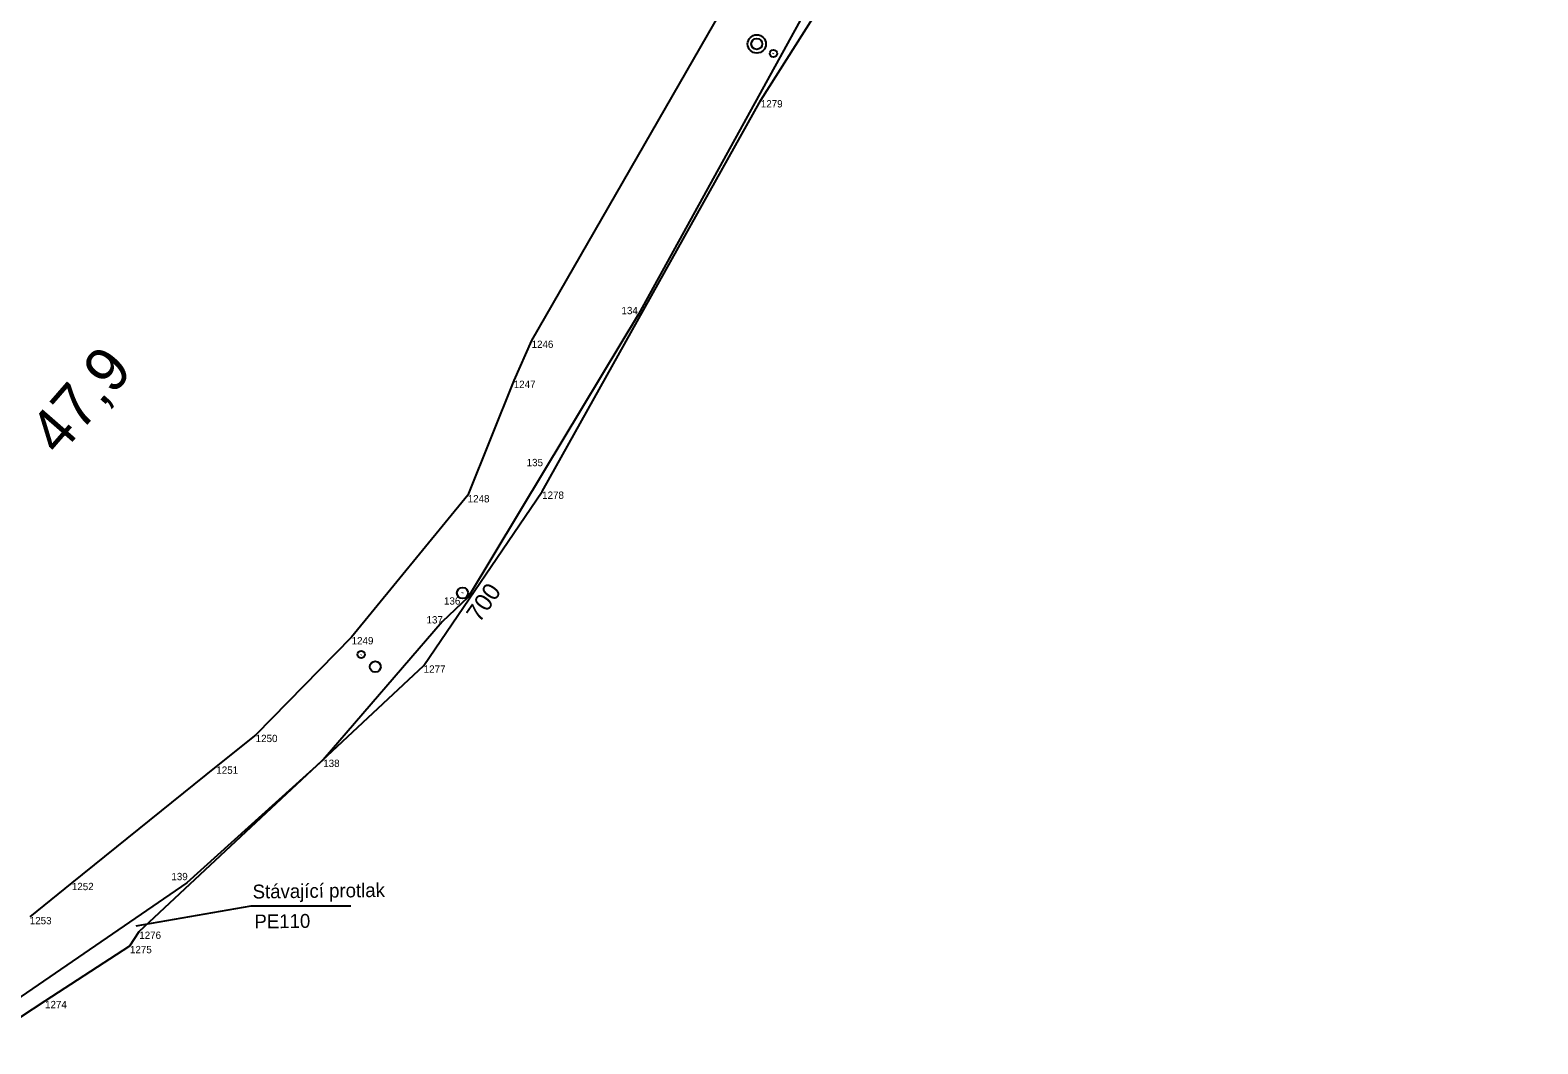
# Model space of a CAD drawing. Extents: x -679938 to -678300, y -1007495 to -1006487.
# Drawn here: x -679528.4 to -679322.3, y -1007219.5 to -1007081 of the extents above; entities that cross this region are included whole.
import ezdxf

# ---------------------------------------------------------------- set-up
doc = ezdxf.new("R2010")
doc.units = 0
for name, color, linetype in [('SSZT nové - lomové body', 7, 'Continuous'), ('SSZT_nové', 7, 'Continuous'), ('Stávající ŽBP', 7, 'Continuous'), ('SŽDC', 7, 'Continuous'), ('SŽDC - body', 7, 'Continuous'), ('Vrstva 7', 7, 'Continuous')]:
    doc.layers.add(name, color=color, linetype=linetype)

msp = doc.modelspace()

# ---------------------------------------------------------------- linework, layer by layer
at = {"layer": 'SSZT nové - lomové body'}
for p, q in [((-679445.24, -1007119.78), (-679445.24, -1007119.78)), ((-679458.14, -1007141.2), (-679458.14, -1007141.2)), ((-679468.52, -1007158.46), (-679468.52, -1007158.46)), ((-679472.05, -1007161.83), (-679472.05, -1007161.83)), ((-679488.31, -1007180.65), (-679488.31, -1007180.65)), ((-679506.94, -1007197.49), (-679506.94, -1007197.49))]:
    msp.add_line(p, q, dxfattribs=at)
at = {"layer": 'SSZT_nové'}
for p, q in [((-679498.2, -1007200.68), (-679513.9, -1007203.39)), ((-679484.54, -1007200.68), (-679498.2, -1007200.68))]:
    msp.add_line(p, q, dxfattribs=at)
msp.add_lwpolyline([(-679220.94, -1006983.3), (-679246.69, -1006986.66), (-679257.12, -1006987.59), (-679263.64, -1006989.78), (-679290.37, -1006993.12), (-679314.41, -1006997.58), (-679339.65, -1007005.39), (-679347.7, -1007008.02), (-679359.02, -1007014.04), (-679374.65, -1007024.99), (-679381.38, -1007029.97), (-679393.78, -1007041.11), (-679406.46, -1007055.73), (-679421.12, -1007075.95), (-679445.24, -1007119.78), (-679458.14, -1007141.2), (-679468.52, -1007158.46), (-679472.05, -1007161.83), (-679488.31, -1007180.65), (-679506.94, -1007197.49), (-679535.13, -1007216.77)], dxfattribs=at)
at = {"layer": 'Stávající ŽBP'}
msp.add_line((-679469.3, -1007157.91), (-679469.25, -1007157.83), dxfattribs=at)
msp.add_circle((-679469.28, -1007157.87), 0.756, dxfattribs=at)
at = {"layer": 'SŽDC'}
for p, q in [((-679433.94, -1007078.32), (-679459.84, -1007123.39)), ((-679428.52, -1007090.53), (-679421.43, -1007079.32)), ((-679458.4, -1007144.01), (-679428.52, -1007090.53)), ((-679459.84, -1007123.39), (-679462.28, -1007128.86)), ((-679462.28, -1007128.86), (-679468.57, -1007144.5)), ((-679468.57, -1007144.5), (-679484.43, -1007163.89)), ((-679474.58, -1007167.77), (-679458.4, -1007144.01)), ((-679484.43, -1007163.89), (-679497.54, -1007177.25)), ((-679513.45, -1007204.14), (-679474.58, -1007167.77)), ((-679497.54, -1007177.25), (-679502.92, -1007181.58)), ((-679502.92, -1007181.58), (-679522.66, -1007197.48)), ((-679522.66, -1007197.48), (-679528.41, -1007202.14)), ((-679514.72, -1007206.1), (-679513.45, -1007204.14)), ((-679526.32, -1007213.61), (-679514.72, -1007206.1)), ((-679535.31, -1007219.48), (-679526.32, -1007213.61))]:
    msp.add_line(p, q, dxfattribs=at)
at = {"layer": 'SŽDC - body'}
for p, q in [((-679428.52, -1007090.53), (-679428.52, -1007090.53)), ((-679459.84, -1007123.39), (-679459.84, -1007123.39)), ((-679462.28, -1007128.86), (-679462.28, -1007128.86)), ((-679468.57, -1007144.5), (-679468.57, -1007144.5)), ((-679458.4, -1007144.01), (-679458.4, -1007144.01)), ((-679484.43, -1007163.89), (-679484.43, -1007163.89)), ((-679474.58, -1007167.77), (-679474.58, -1007167.77)), ((-679497.54, -1007177.25), (-679497.54, -1007177.25)), ((-679502.92, -1007181.58), (-679502.92, -1007181.58)), ((-679522.66, -1007197.48), (-679522.66, -1007197.48)), ((-679513.45, -1007204.14), (-679513.45, -1007204.14)), ((-679514.72, -1007206.1), (-679514.72, -1007206.1)), ((-679526.32, -1007213.61), (-679526.32, -1007213.61))]:
    msp.add_line(p, q, dxfattribs=at)
at = {"layer": 'Vrstva 7'}
for p, q in [((-679426.83, -1007084.22), (-679426.78, -1007084.13)), ((-679483.15, -1007166.33), (-679483.08, -1007166.26))]:
    msp.add_line(p, q, dxfattribs=at)
for centre, radius in [((-679429.07, -1007082.85), 1.25), ((-679429.07, -1007082.85), 0.752), ((-679426.8, -1007084.17), 0.5), ((-679483.12, -1007166.29), 0.5), ((-679481.21, -1007167.95), 0.75)]:
    msp.add_circle(centre, radius, dxfattribs=at)

# ---------------------------------------------------------------- texts
at = {"layer": 'SSZT nové - lomové body'}
for s, p in [('134', (-679447.56, -1007119.78)), ('135', (-679460.52, -1007140.55)), ('136', (-679471.81, -1007159.46)), ('137', (-679474.2, -1007162.04)), ('138', (-679488.31, -1007181.65)), ('139', (-679509.06, -1007197.12))]:
    msp.add_text(s, height=1, dxfattribs=at).set_placement(p)
at = {"layer": 'SSZT_nové'}
for s, p in [('Stávající protlak', (-679497.95, -1007199.63)), ('PE110', (-679497.7, -1007203.72))]:
    msp.add_text(s, height=1.9, rotation=0.7098, dxfattribs=at).set_placement(p)
at = {"layer": 'Stávající ŽBP'}
msp.add_text('700', height=2.4, rotation=55.0368, dxfattribs=at).set_placement((-679466.96, -1007162.03))
at = {"layer": 'SŽDC - body'}
for s, p in [('1279', (-679428.52, -1007091.53)), ('1246', (-679459.84, -1007124.39)), ('1247', (-679462.28, -1007129.86)), ('1248', (-679468.57, -1007145.5)), ('1278', (-679458.4, -1007145.01)), ('1249', (-679484.43, -1007164.89)), ('1277', (-679474.58, -1007168.77)), ('1250', (-679497.54, -1007178.25)), ('1251', (-679502.92, -1007182.58)), ('1252', (-679522.66, -1007198.48)), ('1253', (-679528.41, -1007203.14)), ('1276', (-679513.45, -1007205.14)), ('1275', (-679514.72, -1007207.1)), ('1274', (-679526.32, -1007214.61))]:
    msp.add_text(s, height=1, dxfattribs=at).set_placement(p)
at = {"layer": 'Vrstva 7'}
msp.add_text('47,9', height=6, rotation=48.8994, dxfattribs=at).set_placement((-679524.41, -1007139.33))

doc.saveas('drawing.dxf')
